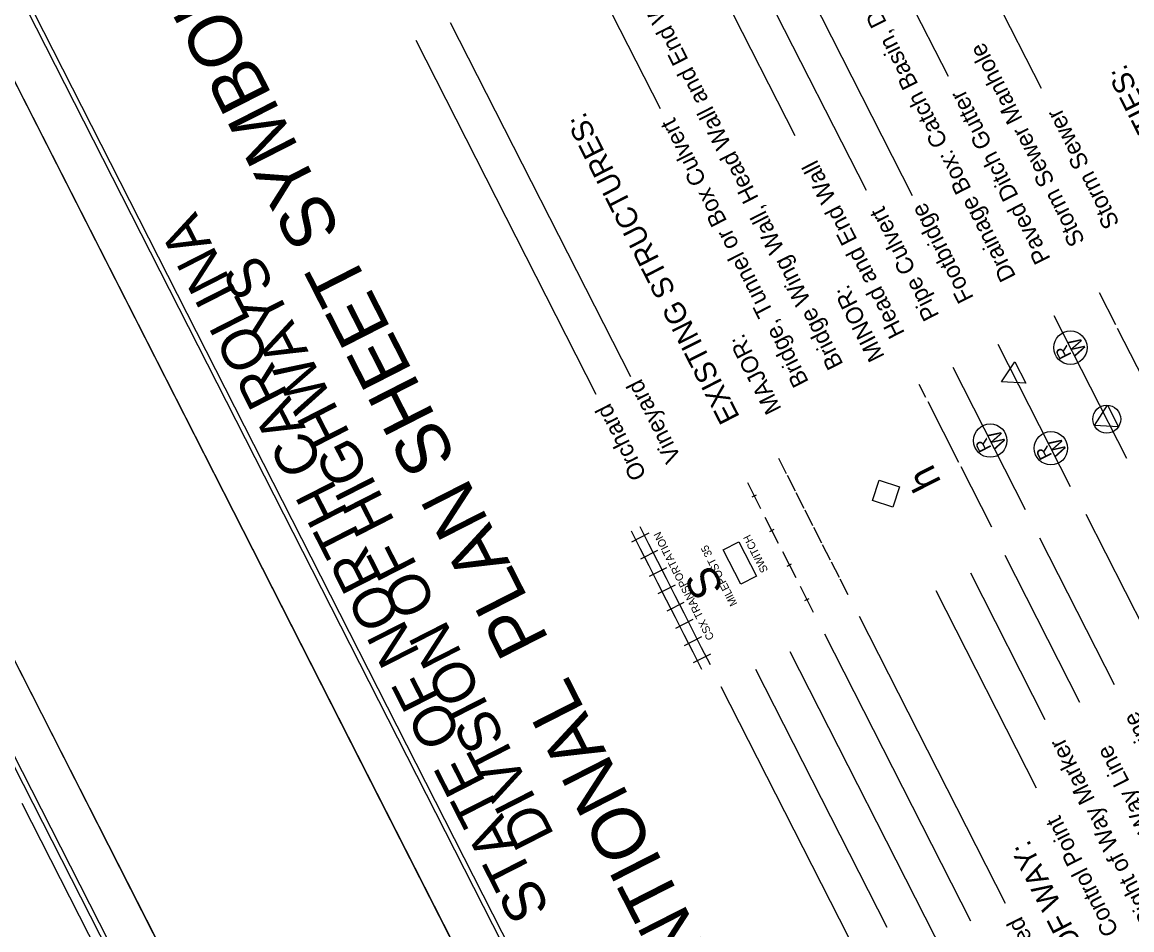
# Model space of a CAD drawing. Extents: x 558484 to 564063, y 513718 to 518374.
# Drawn here: x 559932 to 560504, y 515693 to 516162 of the extents above; entities that cross this region are included whole.
import ezdxf

# ---------------------------------------------------------------- set-up
doc = ezdxf.new("R2010")
doc.units = 0
for name, color, linetype in [('Prop Terminator CELL', 7, 'Continuous'), ('Sheet Cutting Line CELL', 7, 'Continuous'), ('Sheet Plot Border Inside CELL', 7, 'Continuous'), ('Sheet Plot Border Outside CELL', 7, 'Continuous'), ('Sheet Symbology CELL', 7, 'Continuous'), ('Sheet Title CELL', 7, 'Continuous')]:
    doc.layers.add(name, color=color, linetype=linetype)

msp = doc.modelspace()

# ---------------------------------------------------------------- linework, layer by layer
at = {"layer": 'Prop Terminator CELL'}
msp.add_lwpolyline([(560381.21, 515911.51), (560370.69, 515914.93), (560374.11, 515925.45), (560384.63, 515922.03)], close=True, dxfattribs=at)
at = {"layer": 'Sheet Cutting Line CELL'}
for p, q in [((559735.06, 516509.63), (560499.11, 515008.93)), ((560390.41, 514923.75), (559626.36, 516424.45))]:
    msp.add_line(p, q, dxfattribs=at)
at = {"layer": 'Sheet Plot Border Inside CELL'}
for points in [[(561453.47, 515509.41), (560697.36, 516994.51), (559757.11, 516515.8), (560513.21, 515030.7)], [(560364.51, 514925.16), (559608.41, 516410.26), (558668.16, 515931.55), (559424.26, 514446.45)]]:
    msp.add_lwpolyline(points, close=True, dxfattribs=at)
at = {"layer": 'Sheet Plot Border Outside CELL'}
for points in [[(561479.37, 515508.01), (560715.32, 517008.71), (559735.06, 516509.63), (560499.11, 515008.93)], [(558646.11, 515925.37), (559410.15, 514424.68), (560390.41, 514923.75), (559626.36, 516424.45)]]:
    msp.add_lwpolyline(points, close=True, dxfattribs=at)
at = {"layer": 'Sheet Symbology CELL'}
for p, q in [((560383.17, 516274.05), (560457.67, 516127.72)), ((560347.53, 516255.9), (560409.66, 516133.86)), ((560307.93, 516235.74), (560391.18, 516072.24)), ((560290.11, 516226.67), (560367.32, 516075.01)), ((560272.29, 516217.6), (560330.5, 516103.26)), ((560222.76, 516192.38), (560261.07, 516117.15)), ((560152.67, 516161.54), (560245.65, 515978.91)), ((560134.84, 516152.46), (560227.82, 515969.83)), ((560496.28, 516005.5), (560487.83, 516022.1)), ((560501.87, 515936.67), (560464.44, 516010.19)), ((560517.34, 515964.14), (560497.19, 516003.72)), ((560472.91, 515921.92), (560435.48, 515995.44)), ((560449.63, 515910.07), (560412.2, 515983.59)), ((560443.67, 515979.36), (560443.67, 515979.36)), ((560398.18, 515968.04), (560394.77, 515974.72)), ((560415.19, 515934.62), (560399.31, 515965.81)), ((560491.57, 515956.9), (560491.57, 515956.9)), ((560326.3, 515928.64), (560322.22, 515936.66)), ((560330.84, 515919.73), (560326.76, 515927.75)), ((560432.21, 515901.2), (560416.33, 515932.39)), ((560313.02, 515910.65), (560306.21, 515924.02)), ((560308.5, 515916.77), (560310.73, 515917.9)), ((560335.38, 515910.81), (560331.3, 515918.84)), ((560322.09, 515892.83), (560315.29, 515906.2)), ((560339.92, 515901.9), (560335.83, 515909.92)), ((560480.72, 515907.91), (560511.17, 515848.1)), ((560250.77, 515890.18), (560246.23, 515899.09)), ((560255.22, 515892.45), (560250.69, 515901.36)), ((560317.58, 515898.95), (560319.8, 515900.08)), ((560344.45, 515892.99), (560340.37, 515901.01)), ((560255.18, 515898.04), (560246.27, 515893.5)), ((560456.79, 515895.73), (560495.33, 515820.04)), ((560255.31, 515881.27), (560250.77, 515890.18)), ((560259.72, 515889.13), (560250.81, 515884.59)), ((560259.76, 515883.54), (560255.22, 515892.45)), ((560331.17, 515875.01), (560324.36, 515888.37)), ((560348.99, 515884.08), (560344.91, 515892.1)), ((560264.3, 515874.63), (560259.76, 515883.54)), ((560326.65, 515881.12), (560328.88, 515882.26)), ((560353.53, 515875.17), (560349.44, 515883.19)), ((560438.97, 515886.65), (560477.5, 515810.96)), ((560259.84, 515872.36), (560255.31, 515881.27)), ((560264.26, 515880.22), (560255.35, 515875.68)), ((560421.14, 515877.58), (560459.68, 515801.89)), ((560264.38, 515863.45), (560259.84, 515872.36)), ((560268.79, 515871.3), (560259.88, 515866.77)), ((560268.84, 515865.71), (560264.3, 515874.63)), ((560340.24, 515857.18), (560333.44, 515870.55)), ((560358.06, 515866.26), (560353.98, 515874.28)), ((560273.37, 515856.8), (560268.84, 515865.71)), ((560403.32, 515868.51), (560455.14, 515766.72)), ((560268.92, 515854.53), (560264.38, 515863.45)), ((560273.33, 515862.39), (560264.42, 515857.86)), ((560335.72, 515863.3), (560337.95, 515864.43)), ((560273.45, 515845.62), (560268.92, 515854.53)), ((560277.87, 515853.48), (560268.96, 515848.94)), ((560277.91, 515847.89), (560273.37, 515856.8)), ((560363.69, 515855.21), (560439.08, 515707.14)), ((560363.69, 515855.21), (560439.08, 515707.14)), ((560282.45, 515838.98), (560277.91, 515847.89)), ((560277.99, 515836.71), (560273.45, 515845.62)), ((560282.41, 515844.57), (560273.49, 515840.03)), ((560345.86, 515846.14), (560421.25, 515698.06)), ((560282.53, 515827.8), (560277.99, 515836.71)), ((560286.98, 515830.07), (560282.45, 515838.98)), ((560328.04, 515837.07), (560425.55, 515645.55)), ((560286.94, 515835.66), (560278.03, 515831.12)), ((560310.22, 515827.99), (560378.07, 515694.72)), ((560292.39, 515818.92), (560364.27, 515677.75))]:
    msp.add_line(p, q, dxfattribs=at)
for points in [[(559765.05, 516505.82), (560445.62, 515169.1), (561380.42, 515645.03), (560699.85, 516981.75)], [(560449.71, 515975.42), (560437.25, 515976.09), (560444.04, 515986.56)], [(560497.62, 515952.96), (560485.16, 515953.63), (560491.94, 515964.1)], [(560302.6, 515871.68), (560293.53, 515889.51), (560301.64, 515893.64), (560310.71, 515875.81)]]:
    msp.add_lwpolyline(points, close=True, dxfattribs=at)
for centre, radius in [((560472.79, 515993.79), 8.61), ((560491.58, 515956.9), 7.2), ((560431.42, 515945.82), 8.61), ((560462.74, 515941.9), 8.61)]:
    msp.add_circle(centre, radius, dxfattribs=at)
at = {"layer": 'Sheet Title CELL'}
for points in [[(560287.83, 515070.15), (559616.34, 516389.05)], [(560104.16, 515419.88), (559931.75, 515758.52)]]:
    msp.add_lwpolyline(points, dxfattribs=at)

# ---------------------------------------------------------------- texts
at = {"layer": 'Sheet Symbology CELL'}
for s, height, p in [('CONVENTIONAL  PLAN SHEET SYMBOLS', 27.2003, (560343.38, 515569.26)), ('Drainage Box: Catch Basin, DI or JB', 8.75, (560444.88, 516030.6)), ('Bridge Wing Wall, Head Wall and End Wall', 8.75, (560355.78, 515985.22)), ('Storm Sewer Manhole', 8.75, (560480.54, 516048.75)), ('UTILITIES:', 11, (560534.01, 516075.97)), ('Paved Ditch Gutter', 8.75, (560462.72, 516039.68)), ('EXISTING STRUCTURES:', 11, (560302.32, 515958)), ('Bridge, Tunnel or Box Culvert', 8.75, (560337.96, 515976.15)), ('Storm Sewer', 8.75, (560498.36, 516057.83)), ('Head and End Wall', 8.75, (560387.48, 516001.36)), ('Pipe Culvert', 8.75, (560405.29, 516010.43)), ('Footbridge', 8.75, (560423.11, 516019.52)), ('STATE OF NORTH CAROLINA', 21.419, (560204.52, 515704.26)), ('DIVISION OF HIGHWAYS', 21.419, (560206.7, 515742.23)), ('MINOR:', 8.75, (560377.07, 515989.3)), ('MAJOR:', 8.75, (560323.86, 515962.21)), ('W', 6.75, (560481.35, 515992.26)), ('R', 6.75, (560473.57, 515990.02)), ('Vineyard', 8.75, (560272.01, 515937.09)), ('Orchard', 8.75, (560254.19, 515928.02)), ('R', 6.75, (560432.2, 515942.06)), ('W', 6.75, (560439.99, 515944.3)), ('W', 6.75, (560471.3, 515940.38)), ('R', 6.75, (560463.52, 515938.14)), ('h', 15, (560406.32, 515924.5)), ('CSX TRANSPORTATION', 4, (560289.08, 515844.11)), ('SWITCH', 4, (560316.89, 515878.91)), ('MILEPOST 35', 4, (560301.01, 515861.62)), ('S', 16.5, (560294.31, 515869.44)), ('Proposed Right of Way Line', 8.75, (560573.25, 515677.01)), ('Existing Right of Way Marker', 8.75, (560537.6, 515658.86)), ('Existing Right of Way Line', 8.75, (560555.43, 515667.94)), ('Baseline Control Point', 8.75, (560519.78, 515649.79)), ('RIGHT OF WAY:', 11, (560501.96, 515640.71)), ('RR Dismantled', 8.75, (560483.03, 515630.77))]:
    msp.add_text(s, height=height, rotation=116.9819, dxfattribs=at).set_placement(p)

doc.saveas('drawing.dxf')
